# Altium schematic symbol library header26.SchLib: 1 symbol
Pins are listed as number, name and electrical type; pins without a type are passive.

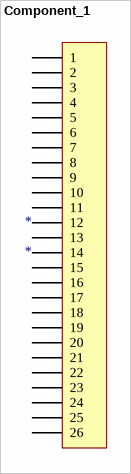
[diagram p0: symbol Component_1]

## Component_1
designator *
pins: 1, 2, 3, 4, 5, 6, 7, 8, 9, 10, 11, 12, 13, 14, 15, 16, 17, 18, 19, 20, 21, 22, 23, 24, 25, 26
